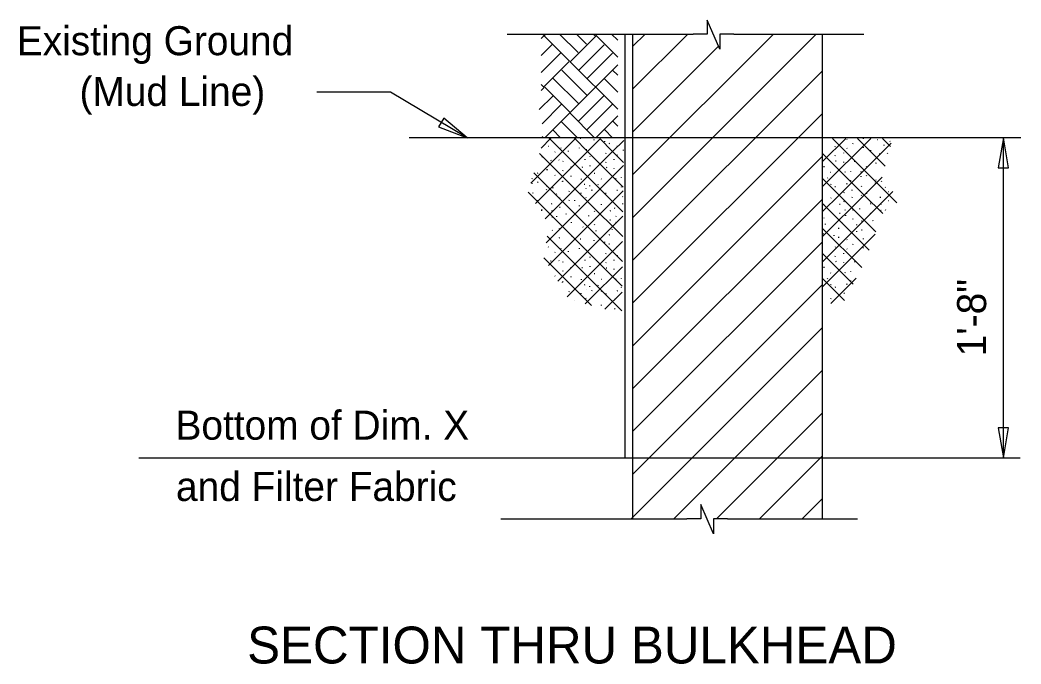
# Model space of a CAD drawing. Extents: x 111162.5 to 111216.6, y 110741.1 to 110776.1.
# Drawn here: x 111171.79 to 111176.99, y 110765.36 to 110768.71 of the extents above; entities that cross this region are included whole.
import ezdxf

# ---------------------------------------------------------------- set-up
doc = ezdxf.new("R2010")
doc.units = 0
for name, color, linetype in [('Border', 7, 'Continuous'), ('Patterning', 7, 'Continuous'), ('PlotBorder_dp', 7, 'Continuous'), ('SheetBorder_dp', 7, 'Continuous'), ('TextMisc', 7, 'Continuous')]:
    doc.layers.add(name, color=color, linetype=linetype)

msp = doc.modelspace()

# ---------------------------------------------------------------- linework, layer by layer
at = {"layer": 'Border'}
msp.add_line((111174.9351, 110766.4287), (111174.9351, 110768.6352), dxfattribs=at)
at = {"layer": 'Patterning'}
for p, q in [((111174.3208, 110768.6352), (111175.2889, 110768.6352)), ((111175.4996, 110768.6352), (111176.1761, 110768.6352)), ((111176.9026, 110766.4287), (111176.9026, 110768.0954)), ((111172.4028, 110766.4287), (111176.9898, 110766.4287)), ((111174.2879, 110766.112), (111175.256, 110766.112)), ((111175.4667, 110766.112), (111176.1432, 110766.112))]:
    msp.add_line(p, q, dxfattribs=at)
for points in [[(111175.4996, 110768.6352), (111175.4277, 110768.6352), (111175.4277, 110768.557), (111175.3608, 110768.7082), (111175.3608, 110768.6352), (111175.2889, 110768.6352)], [(111174.1114, 110768.0954), (111173.7127, 110768.3328), (111173.3306, 110768.3328)], [(111175.4667, 110766.112), (111175.3948, 110766.112), (111175.3948, 110766.0339), (111175.3279, 110766.1851), (111175.3279, 110766.112), (111175.256, 110766.112)]]:
    msp.add_lwpolyline(points, dxfattribs=at)
for points in [[(111174.1114, 110768.0954), (111173.9907, 110768.198), (111173.9637, 110768.1526)], [(111176.9026, 110768.0954), (111176.8761, 110767.9392), (111176.9291, 110767.9392)], [(111176.9026, 110766.4288), (111176.9291, 110766.5849), (111176.8761, 110766.5849)]]:
    msp.add_lwpolyline(points, close=True, dxfattribs=at)
at = {"layer": 'PlotBorder_dp'}
for p, q in [((111174.9745, 110766.112), (111174.9745, 110768.6352)), ((111175.9589, 110768.6352), (111175.9589, 110766.112))]:
    msp.add_line(p, q, dxfattribs=at)
at = {"layer": 'TextMisc'}
for p, q in [((111174.5215, 110768.6352), (111174.4974, 110768.6111)), ((111174.6454, 110768.4941), (111174.5043, 110768.6352)), ((111174.5929, 110768.6352), (111174.6897, 110768.5384)), ((111174.6811, 110768.6352), (111174.7338, 110768.5825)), ((111174.7696, 110768.6352), (111174.7781, 110768.6268)), ((111174.7866, 110768.6352), (111174.7809, 110768.6295)), ((111174.8957, 110768.6029), (111174.8635, 110768.6352)), ((111174.9745, 110767.6808), (111175.9289, 110768.6352)), ((111174.9745, 110768.3491), (111175.2606, 110768.6352)), ((111174.9745, 110767.9036), (111175.7061, 110768.6352)), ((111174.9745, 110768.5718), (111175.0379, 110768.6352)), ((111174.557, 110768.5825), (111174.4974, 110768.5229)), ((111174.7809, 110768.624), (111174.6482, 110768.4913)), ((111174.8957, 110768.5146), (111174.7836, 110768.6268)), ((111174.6011, 110768.5384), (111174.4974, 110768.4346)), ((111174.8252, 110768.5797), (111174.6925, 110768.447)), ((111174.8693, 110768.5356), (111174.7366, 110768.4029)), ((111174.9745, 110768.1263), (111175.4208, 110768.5726)), ((111174.6454, 110768.4941), (111174.5133, 110768.362)), ((111174.8957, 110768.2438), (111174.6482, 110768.4913)), ((111174.7367, 110768.3154), (111174.6045, 110768.4476)), ((111174.8957, 110768.4744), (111174.6483, 110768.2269)), ((111174.8689, 110768.4474), (111174.8957, 110768.4206)), ((111174.9745, 110767.4581), (111175.9589, 110768.4425)), ((111174.6925, 110768.2711), (111174.5602, 110768.4033)), ((111174.8247, 110768.4033), (111174.8957, 110768.3323)), ((111174.4974, 110768.3723), (111174.5105, 110768.3591)), ((111174.5133, 110768.3564), (111174.4974, 110768.3405)), ((111174.6483, 110768.2269), (111174.5161, 110768.3592)), ((111174.5576, 110768.3121), (111174.4869, 110768.2415)), ((111174.8246, 110768.3149), (111174.6925, 110768.1828)), ((111174.8687, 110768.2708), (111174.7366, 110768.1387)), ((111174.6017, 110768.268), (111174.502, 110768.1683)), ((111174.6456, 110768.2241), (111174.5169, 110768.0954)), ((111174.6456, 110768.2241), (111174.7742, 110768.0954)), ((111174.9745, 110767.2354), (111175.9589, 110768.2198)), ((111174.6013, 110768.1799), (111174.6857, 110768.0954)), ((111174.8957, 110768.2092), (111174.7819, 110768.0954)), ((111174.8957, 110768.1564), (111174.872, 110768.1801)), ((111174.5572, 110768.1357), (111174.5975, 110768.0954)), ((111174.8681, 110768.0954), (111174.8278, 110768.1357)), ((111176.9941, 110768.0954), (111173.8096, 110768.0954)), ((111174.4964, 110768.0417), (111174.5484, 110768.0937)), ((111174.5089, 110768.0954), (111174.502, 110768.1023)), ((111174.6087, 110768.0238), (111174.5387, 110768.0938)), ((111174.6087, 110768.0238), (111174.6773, 110768.0923)), ((111174.7387, 110768.024), (111174.6703, 110768.0924)), ((111174.7032, 110768.0914), (111174.6994, 110768.0906)), ((111174.7389, 110768.0238), (111174.8062, 110768.091)), ((111174.7724, 110768.0823), (111174.7731, 110768.0854)), ((111174.8691, 110768.0238), (111174.8018, 110768.0911)), ((111174.8281, 110768.074), (111174.8288, 110768.0771)), ((111174.8536, 110768.0651), (111174.8491, 110768.0643)), ((111174.8691, 110768.0238), (111174.927, 110768.0816)), ((111175.9638, 110767.9727), (111176.083, 110768.0919)), ((111175.9638, 110767.8425), (111176.2132, 110768.0919)), ((111176.3084, 110767.797), (111176.0135, 110768.0919)), ((111176.0888, 110768.0865), (111176.0881, 110768.088)), ((111176.1197, 110768.0633), (111176.1204, 110768.0663)), ((111176.2875, 110767.948), (111176.1437, 110768.0919)), ((111176.1746, 110768.0903), (111176.1749, 110768.0919)), ((111176.2468, 110768.0836), (111176.2453, 110768.0843)), ((111176.3087, 110768.0571), (111176.2739, 110768.0919)), ((111176.3087, 110768.0571), (111176.3178, 110768.0662)), ((111176.3129, 110768.0752), (111176.3122, 110768.0767)), ((111174.4435, 110767.8585), (111174.6087, 110768.0238)), ((111174.4677, 110767.7525), (111174.7389, 110768.0238)), ((111174.7389, 110767.7633), (111174.4884, 110768.0139)), ((111174.536, 110768.0493), (111174.5345, 110768.05)), ((111174.5706, 110768.0222), (111174.5676, 110768.0207)), ((111174.6021, 110768.041), (111174.6014, 110768.0425)), ((111174.7389, 110767.8935), (111174.6087, 110768.0238)), ((111174.639, 110768.0244), (111174.6397, 110768.0274)), ((111174.6964, 110768.0405), (111174.6972, 110768.0434)), ((111174.7326, 110768.0327), (111174.7333, 110768.0358)), ((111174.9244, 110767.8383), (111174.7389, 110768.0238)), ((111174.7389, 110767.8935), (111174.8691, 110768.0238)), ((111174.8333, 110768.0139), (111174.8348, 110768.0169)), ((111174.9258, 110767.9671), (111174.8691, 110768.0238)), ((111174.8949, 110768.0522), (111174.8942, 110768.0537)), ((111174.9258, 110768.029), (111174.9265, 110768.0317)), ((111176.1785, 110767.7967), (111175.9638, 110768.0114)), ((111176.0272, 110768.0482), (111176.0287, 110768.0512)), ((111176.0483, 110767.7967), (111176.3087, 110768.0572)), ((111176.0716, 110768.0144), (111176.0716, 110768.0174)), ((111176.0888, 110768.0392), (111176.0881, 110768.0407)), ((111176.1746, 110768.043), (111176.1754, 110768.0467)), ((111176.2122, 110768.0278), (111176.2129, 110768.0309)), ((111176.2595, 110768.0106), (111176.2558, 110768.0099)), ((111176.2813, 110768.0564), (111176.2783, 110768.055)), ((111176.3017, 110768.0121), (111176.3002, 110768.0144)), ((111176.3155, 110768.0504), (111176.3087, 110768.0572)), ((111174.5014, 110767.9936), (111174.5021, 110767.9966)), ((111174.5488, 110767.9763), (111174.545, 110767.9756)), ((111174.5909, 110767.9778), (111174.5894, 110767.9801)), ((111174.6096, 110767.971), (111174.6112, 110767.974)), ((111174.7257, 110767.9801), (111174.7265, 110767.9831)), ((111174.7514, 110767.9951), (111174.7521, 110767.9981)), ((111174.8333, 110767.9666), (111174.8348, 110767.9696)), ((111174.8777, 110767.9801), (111174.8777, 110767.9831)), ((111174.8949, 110768.0049), (111174.8942, 110768.0064)), ((111174.9745, 110767.0126), (111175.9589, 110767.997)), ((111176.0272, 110768.0008), (111176.0287, 110768.0038)), ((111176.0324, 110767.9737), (111176.0295, 110767.973)), ((111176.0716, 110767.967), (111176.0716, 110767.97)), ((111176.1302, 110767.9722), (111176.1265, 110767.9715)), ((111176.2385, 110767.9625), (111176.24, 110767.9655)), ((111176.24, 110767.961), (111176.2407, 110767.964)), ((111174.7389, 110767.6331), (111174.4592, 110767.9128)), ((111174.4788, 110767.9102), (111174.4811, 110767.9131)), ((111174.5277, 110767.9282), (111174.5292, 110767.9312)), ((111174.5292, 110767.9267), (111174.5299, 110767.9297)), ((111174.6096, 110767.9237), (111174.6112, 110767.9267)), ((111174.6531, 110767.9418), (111174.6493, 110767.941)), ((111174.7123, 110767.9418), (111174.7085, 110767.941)), ((111174.7389, 110767.7633), (111174.9256, 110767.95)), ((111174.7514, 110767.947), (111174.7521, 110767.95)), ((111174.7769, 110767.9094), (111174.7724, 110767.9094)), ((111174.8386, 110767.9395), (111174.8356, 110767.9388)), ((111174.8777, 110767.9327), (111174.8777, 110767.9357)), ((111175.9708, 110767.9437), (111175.9663, 110767.9437)), ((111176.0046, 110767.9144), (111176.0032, 110767.9151)), ((111176.0798, 110767.9159), (111176.0806, 110767.9189)), ((111176.1091, 110767.9204), (111176.1084, 110767.9219)), ((111176.1618, 110767.9159), (111176.1625, 110767.9189)), ((111176.1896, 110767.9444), (111176.1919, 110767.9474)), ((111174.451, 110767.8816), (111174.4517, 110767.8846)), ((111174.451, 110767.8575), (111174.4517, 110767.8605)), ((111174.4788, 110767.8628), (111174.4811, 110767.8658)), ((111174.5186, 110767.6732), (111174.7389, 110767.8935)), ((111174.5706, 110767.8981), (111174.5691, 110767.9004)), ((111174.6089, 110767.8658), (111174.6082, 110767.8673)), ((111174.612, 110767.8681), (111174.6089, 110767.8681)), ((111174.6531, 110767.8944), (111174.6493, 110767.8936)), ((111174.7066, 110767.8786), (111174.7074, 110767.8816)), ((111174.9229, 110767.7095), (111174.7389, 110767.8935)), ((111174.7942, 110767.85), (111174.7949, 110767.853)), ((111174.8108, 110767.8801), (111174.8093, 110767.8808)), ((111174.8859, 110767.8816), (111174.8867, 110767.8846)), ((111174.9153, 110767.8861), (111174.9145, 110767.8876)), ((111176.0483, 110767.7967), (111175.9638, 110767.8812)), ((111175.9881, 110767.8843), (111175.9888, 110767.8872)), ((111176.0054, 110767.8527), (111176.0069, 110767.8557)), ((111176.0888, 110767.8557), (111176.0851, 110767.8542)), ((111176.1091, 110767.873), (111176.1084, 110767.8745)), ((111176.1618, 110767.8918), (111176.1625, 110767.8948)), ((111176.1785, 110767.7967), (111176.2718, 110767.89)), ((111176.1896, 110767.8971), (111176.1919, 110767.9)), ((111176.2363, 110767.858), (111176.2377, 110767.861)), ((111176.24, 110767.8737), (111176.2407, 110767.8767)), ((111176.2686, 110767.8677), (111176.2701, 110767.8715)), ((111174.7387, 110767.5031), (111174.43, 110767.8118)), ((111174.454, 110767.8071), (111174.4556, 110767.8109)), ((111174.5255, 110767.8237), (111174.5269, 110767.8267)), ((111174.5292, 110767.8395), (111174.5299, 110767.8425)), ((111174.5578, 110767.8334), (111174.5593, 110767.8372)), ((111174.5773, 110767.8011), (111174.5781, 110767.8041)), ((111174.6428, 110767.8162), (111174.6443, 110767.8192)), ((111174.7051, 110767.8056), (111174.7058, 110767.8087)), ((111174.7243, 110767.8522), (111174.7205, 110767.8515)), ((111174.7311, 110767.8297), (111174.7306, 110767.8305)), ((111174.7389, 110767.6331), (111174.9241, 110767.8183)), ((111174.7498, 110767.8432), (111174.7506, 110767.8462)), ((111174.7612, 110767.8214), (111174.7627, 110767.8252)), ((111174.8115, 110767.8184), (111174.813, 110767.8214)), ((111174.8356, 110767.8056), (111174.8319, 110767.8049)), ((111174.8949, 110767.8214), (111174.8912, 110767.8199)), ((111174.9153, 110767.8388), (111174.9145, 110767.8403)), ((111176.0295, 110767.8399), (111176.0257, 110767.8391)), ((111176.0754, 110767.8083), (111176.0731, 110767.8106)), ((111176.1152, 110767.8212), (111176.116, 110767.8241)), ((111176.1648, 110767.8414), (111176.1664, 110767.8451)), ((111176.1919, 110767.8024), (111176.1926, 110767.8053)), ((111176.2881, 110767.8354), (111176.2889, 110767.8384)), ((111176.3062, 110767.8136), (111176.3039, 110767.8143)), ((111176.3087, 110767.7967), (111176.3281, 110767.8161)), ((111174.4811, 110767.7681), (111174.4818, 110767.771)), ((111174.5231, 110767.5474), (111174.7389, 110767.7633)), ((111174.5533, 110767.7507), (111174.5495, 110767.75)), ((111174.5954, 110767.7793), (111174.5932, 110767.7801)), ((111174.6428, 110767.7688), (111174.6443, 110767.7718)), ((111174.6722, 110767.7671), (111174.673, 110767.7702)), ((111174.7311, 110767.7823), (111174.7303, 110767.7838)), ((111174.9215, 110767.5807), (111174.7389, 110767.7633)), ((111174.8111, 110767.7458), (111174.8119, 110767.7487)), ((111174.8815, 110767.7741), (111174.8792, 110767.7763)), ((111174.9213, 110767.7869), (111174.9221, 110767.7898)), ((111174.9221, 110767.75), (111174.9228, 110767.753)), ((111174.9745, 110766.7899), (111175.9589, 110767.7743)), ((111175.9638, 110767.4518), (111176.3087, 110767.7967)), ((111175.9638, 110767.7122), (111176.0483, 110767.7967)), ((111175.9638, 110767.582), (111176.1785, 110767.7967)), ((111176.2045, 110767.5102), (111175.9638, 110767.7509)), ((111176.005, 110767.7801), (111176.0058, 110767.783)), ((111176.2396, 110767.6053), (111176.0483, 110767.7967)), ((111176.0754, 110767.761), (111176.0731, 110767.7632)), ((111176.116, 110767.7843), (111176.1167, 110767.7873)), ((111176.1648, 110767.794), (111176.1664, 110767.7978)), ((111176.2749, 110767.7003), (111176.1785, 110767.7967)), ((111176.2106, 110767.7489), (111176.2122, 110767.752)), ((111176.2122, 110767.7542), (111176.2129, 110767.7572)), ((111176.2641, 110767.785), (111176.2602, 110767.7843)), ((111176.2651, 110767.7472), (111176.2659, 110767.7501)), ((111176.3062, 110767.7662), (111176.3039, 110767.767)), ((111176.3488, 110767.7566), (111176.3087, 110767.7967)), ((111174.4999, 110767.7146), (111174.5014, 110767.7177)), ((111174.5014, 110767.7199), (111174.5021, 110767.723)), ((111174.5543, 110767.7129), (111174.5551, 110767.7159)), ((111174.5954, 110767.7319), (111174.5932, 110767.7327)), ((111174.6277, 110767.6974), (111174.6285, 110767.7004)), ((111174.6739, 110767.6952), (111174.6754, 110767.6982)), ((111174.696, 110767.7388), (111174.6968, 110767.7418)), ((111174.7754, 110767.7109), (111174.7761, 110767.7139)), ((111174.8589, 110767.7139), (111174.8551, 110767.7131)), ((111174.8815, 110767.7267), (111174.8792, 110767.729)), ((111175.9693, 110767.7451), (111175.97, 110767.7482)), ((111176.0528, 110767.7482), (111176.049, 110767.7474)), ((111176.0528, 110767.7009), (111176.049, 110767.7001)), ((111176.0798, 110767.7188), (111176.0806, 110767.7219)), ((111176.1197, 110767.7188), (111176.1204, 110767.7219)), ((111176.155, 110767.7238), (111176.1558, 110767.7267)), ((111176.2106, 110767.7016), (111176.2122, 110767.7046)), ((111176.2671, 110767.7166), (111176.2641, 110767.7158)), ((111176.2896, 110767.7181), (111176.2903, 110767.7211)), ((111174.5563, 110767.6823), (111174.5533, 110767.6816)), ((111174.5788, 110767.6838), (111174.5795, 110767.6868)), ((111174.6545, 110767.653), (111174.6559, 110767.656)), ((111174.7389, 110767.5029), (111174.9227, 110767.6867)), ((111174.7453, 110767.6868), (111174.746, 110767.6898)), ((111174.7754, 110767.6417), (111174.7761, 110767.6447)), ((111174.8589, 110767.6666), (111174.8551, 110767.6658)), ((111174.8859, 110767.6846), (111174.8867, 110767.6876)), ((111174.8884, 110767.6543), (111174.8892, 110767.6573)), ((111175.9693, 110767.676), (111175.97, 110767.679)), ((111175.9768, 110767.644), (111175.9776, 110767.6469)), ((111176.061, 110767.652), (111176.0618, 110767.6549)), ((111176.0823, 110767.6886), (111176.0831, 110767.6915)), ((111176.1197, 110767.6715), (111176.1204, 110767.6745)), ((111176.1678, 110767.6617), (111176.1648, 110767.6609)), ((111176.2257, 110767.6617), (111176.2235, 110767.6639)), ((111174.554, 110767.6116), (111174.5556, 110767.6146)), ((111174.5924, 110767.6214), (111174.5894, 110767.6199)), ((111174.6087, 110767.5029), (111174.7389, 110767.6331)), ((111174.7153, 110767.6297), (111174.7138, 110767.6319)), ((111174.8691, 110767.5029), (111174.7389, 110767.6331)), ((111174.783, 110767.6097), (111174.7837, 110767.6127)), ((111174.8671, 110767.6177), (111174.8679, 110767.6206)), ((111176.1654, 110767.4191), (111175.9638, 110767.6207)), ((111175.9638, 110767.3216), (111176.2349, 110767.5927)), ((111175.9663, 110767.5932), (111175.967, 110767.5963)), ((111176.0475, 110767.6233), (111176.043, 110767.6226)), ((111176.1399, 110767.6407), (111176.1407, 110767.6436)), ((111176.1399, 110767.6053), (111176.1407, 110767.6083)), ((111176.1678, 110767.6143), (111176.1648, 110767.6136)), ((111176.231, 110767.6098), (111176.2317, 110767.6128)), ((111174.6087, 110767.5029), (111174.5283, 110767.5833)), ((111174.5924, 110767.574), (111174.5894, 110767.5726)), ((111174.6561, 110767.5823), (111174.6546, 110767.5846)), ((111174.7032, 110767.5681), (111174.6994, 110767.5673)), ((111174.7724, 110767.559), (111174.7731, 110767.562)), ((111174.8281, 110767.5507), (111174.8288, 110767.5538)), ((111174.8536, 110767.589), (111174.8491, 110767.5883)), ((111174.8536, 110767.5417), (111174.8491, 110767.5409)), ((111174.8691, 110767.5029), (111174.9213, 110767.555)), ((111174.9745, 110766.5672), (111175.9589, 110767.5515)), ((111176.022, 110767.585), (111176.0227, 110767.588)), ((111176.0475, 110767.576), (111176.043, 110767.5752)), ((111176.0888, 110767.5632), (111176.0881, 110767.5647)), ((111176.1197, 110767.5399), (111176.1204, 110767.5429)), ((111176.1746, 110767.5669), (111176.1754, 110767.5707)), ((111174.536, 110767.526), (111174.5345, 110767.5267)), ((111174.5351, 110767.4293), (111174.6087, 110767.5029)), ((111174.5706, 110767.4988), (111174.5676, 110767.4974)), ((111174.584, 110767.3479), (111174.7389, 110767.5029)), ((111174.6021, 110767.5176), (111174.6014, 110767.5191)), ((111174.7389, 110767.3726), (111174.6087, 110767.5029)), ((111174.639, 110767.5011), (111174.6397, 110767.5041)), ((111174.6964, 110767.5171), (111174.6972, 110767.5201)), ((111174.7326, 110767.5094), (111174.7333, 110767.5124)), ((111174.9187, 110767.323), (111174.7389, 110767.5029)), ((111174.7389, 110767.3726), (111174.8691, 110767.5029)), ((111174.8333, 110767.4905), (111174.8348, 110767.4936)), ((111174.9201, 110767.4518), (111174.8691, 110767.5029)), ((111174.8949, 110767.5289), (111174.8942, 110767.5304)), ((111176.1209, 110767.3334), (111175.9638, 110767.4905)), ((111176.0272, 110767.5248), (111176.0287, 110767.5279)), ((111176.0716, 110767.491), (111176.0716, 110767.494)), ((111176.0888, 110767.5158), (111176.0881, 110767.5173)), ((111176.1746, 110767.5196), (111176.1754, 110767.5233)), ((111174.7389, 110767.2424), (111174.5117, 110767.4697)), ((111174.5488, 110767.453), (111174.545, 110767.4523)), ((111174.5909, 110767.4545), (111174.5894, 110767.4568)), ((111174.6096, 110767.4477), (111174.6112, 110767.4507)), ((111174.7257, 110767.4568), (111174.7265, 110767.4597)), ((111174.7514, 110767.4718), (111174.7521, 110767.4748)), ((111174.8333, 110767.4432), (111174.8348, 110767.4462)), ((111174.8777, 110767.4568), (111174.8777, 110767.4597)), ((111174.8949, 110767.4816), (111174.8942, 110767.4831)), ((111176.0272, 110767.4775), (111176.0287, 110767.4805)), ((111176.0324, 110767.4504), (111176.0295, 110767.4497)), ((111176.0716, 110767.4436), (111176.0716, 110767.4466)), ((111176.1302, 110767.4489), (111176.1265, 110767.4481)), ((111174.6096, 110767.4003), (111174.6112, 110767.4034)), ((111174.6531, 110767.4184), (111174.6493, 110767.4176)), ((111174.7123, 110767.4184), (111174.7085, 110767.4176)), ((111174.7389, 110767.2424), (111174.9198, 110767.4233)), ((111174.7514, 110767.4236), (111174.7521, 110767.4267)), ((111174.7769, 110767.386), (111174.7724, 110767.386)), ((111174.8386, 110767.4161), (111174.8356, 110767.4154)), ((111174.8777, 110767.4094), (111174.8777, 110767.4124)), ((111175.9708, 110767.4203), (111175.9663, 110767.4203)), ((111176.0046, 110767.391), (111176.0032, 110767.3917)), ((111176.0798, 110767.3925), (111176.0806, 110767.3955)), ((111176.1091, 110767.397), (111176.1084, 110767.3985)), ((111174.5706, 110767.3748), (111174.5691, 110767.3771)), ((111174.6089, 110767.3424), (111174.6082, 110767.3439)), ((111174.612, 110767.3447), (111174.6089, 110767.3447)), ((111174.6328, 110767.2665), (111174.7389, 110767.3726)), ((111174.6531, 110767.371), (111174.6493, 110767.3702)), ((111174.7066, 110767.3553), (111174.7074, 110767.3582)), ((111174.9173, 110767.1942), (111174.7389, 110767.3726)), ((111174.8108, 110767.3568), (111174.8093, 110767.3575)), ((111174.8859, 110767.3582), (111174.8867, 110767.3612)), ((111174.9153, 110767.3627), (111174.9145, 110767.3642)), ((111176.0483, 110767.2758), (111175.9638, 110767.3603)), ((111175.9881, 110767.3609), (111175.9888, 110767.3639)), ((111176.0054, 110767.3293), (111176.0069, 110767.3323)), ((111176.0483, 110767.2758), (111176.1372, 110767.3648)), ((111176.0888, 110767.3323), (111176.0851, 110767.3308)), ((111176.1091, 110767.3497), (111176.1084, 110767.3512)), ((111174.6428, 110767.2928), (111174.6443, 110767.2958)), ((111174.7051, 110767.2823), (111174.7058, 110767.2854)), ((111174.7243, 110767.3289), (111174.7205, 110767.3282)), ((111174.7311, 110767.3063), (111174.7306, 110767.3072)), ((111174.7498, 110767.3198), (111174.7506, 110767.3229)), ((111174.7612, 110767.2981), (111174.7627, 110767.3018)), ((111174.7942, 110767.3267), (111174.7949, 110767.3296)), ((111174.8115, 110767.2951), (111174.813, 110767.2981)), ((111174.8291, 110767.2024), (111174.9184, 110767.2917)), ((111174.8356, 110767.2823), (111174.8319, 110767.2815)), ((111174.8949, 110767.2981), (111174.8912, 110767.2966)), ((111174.9153, 110767.3154), (111174.9145, 110767.3169)), ((111174.9745, 110766.3444), (111175.9589, 110767.3288)), ((111176.0295, 110767.3166), (111176.0257, 110767.3158)), ((111176.0754, 110767.285), (111176.0731, 110767.2873)), ((111174.6726, 110767.2454), (111174.673, 110767.2468)), ((111174.727, 110767.2305), (111174.7389, 110767.2424)), ((111174.7311, 110767.259), (111174.7303, 110767.2605)), ((111174.7599, 110767.2214), (111174.7389, 110767.2424)), ((111174.8815, 110767.2507), (111174.8792, 110767.253)), ((111176.005, 110767.2567), (111176.0058, 110767.2597)), ((111176.0054, 110767.233), (111176.0483, 110767.2758)), ((111176.0764, 110767.2477), (111176.0483, 110767.2758)), ((111174.8111, 110767.2225), (111174.8119, 110767.2254)), ((111174.8815, 110767.2034), (111174.8792, 110767.2056)), ((111174.9648, 110766.112), (111175.9589, 110767.1061)), ((111175.1875, 110766.112), (111175.9589, 110766.8833)), ((111175.4103, 110766.112), (111175.9589, 110766.6606)), ((111175.633, 110766.112), (111175.9589, 110766.4378)), ((111175.8558, 110766.112), (111175.9589, 110766.2151))]:
    msp.add_line(p, q, dxfattribs=at)

# ---------------------------------------------------------------- texts
at = {"layer": 'Patterning'}
for s, p in [('Existing Ground', (111171.7687, 110768.5249)), ('(Mud Line)', (111172.095, 110768.2609)), ('Bottom of Dim. X', (111172.5943, 110766.5234)), ('and Filter Fabric', (111172.5968, 110766.2042))]:
    msp.add_text(s, height=0.1512, dxfattribs=at).set_placement(p)
at = {"layer": 'SheetBorder_dp'}
msp.add_text('1\'-8"', height=0.1512, rotation=90, dxfattribs=at).set_placement((111176.8129, 110766.9573))
msp.add_text('SECTION THRU BULKHEAD', height=0.192, dxfattribs=at).set_placement((111172.9673, 110765.3582))

doc.saveas('drawing.dxf')
